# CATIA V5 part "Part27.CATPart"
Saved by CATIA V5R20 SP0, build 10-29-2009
Part number: 8PF1042WB-00-20130117
Revision: ANY
Definition: UNKNOWN
Nomenclature: 8PF1042WB-00-20130117
Source: Unknown
Bounding box of the stored display mesh (mm): x 1681.921 to 1881.921, y 1457.713 to 1464.638, z 0 to 10
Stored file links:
  C:\Users\Utente\Desktop\IO LAVORO\3D X SITO CF\CUMSA\3D files PF\PF 104200\Part27.CATPart
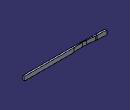
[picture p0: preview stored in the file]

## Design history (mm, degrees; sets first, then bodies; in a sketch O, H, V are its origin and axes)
Body1 "Cortar-Extruir1" (main body)
  Solid1: solid without history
